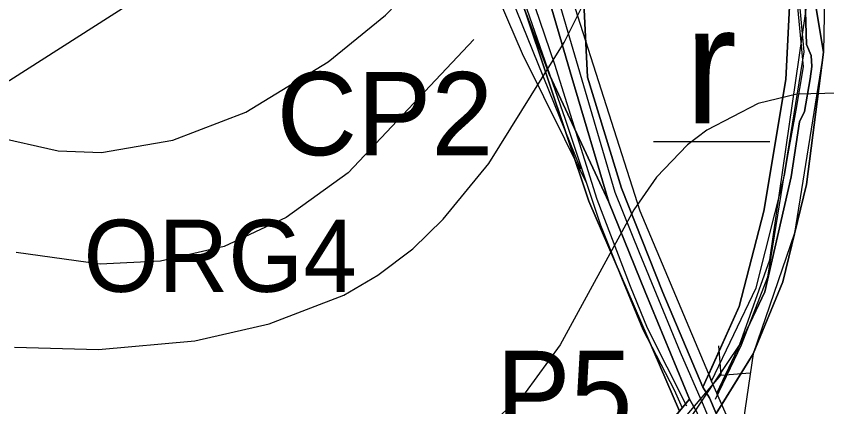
# Model space of a CAD drawing. Extents: x -1900516 to -575031, y -3809306 to -1157387.
# Drawn here: x -577969.3 to -577823.3, y -1159157.5 to -1159087.1 of the extents above; entities that cross this region are included whole.
import ezdxf

# ---------------------------------------------------------------- set-up
doc = ezdxf.new("R2010")
doc.units = 0
for name, color, linetype in [('01_PARCELY_NÁVRH_PC', 7, 'Continuous'), ('01_PARCELY_NÁVRH_VHO', 7, 'Continuous'), ('01_PARCELY_NÁVRH_ŽP', 7, 'Continuous'), ('01_VRSTEVNICE', 7, 'Continuous'), ('01_ZASTAV_PLOCHY', 7, 'Continuous'), ('02_KULTURY STAV', 7, 'Continuous'), ('03_PC_NÁVRH', 7, 'Continuous'), ('03_PC_OBJEKTY_NÁVRH', 7, 'Continuous'), ('04_ZPF_OP_ORGAN', 7, 'Continuous'), ('05_VHO_V_TOK', 7, 'Continuous'), ('06_ÚSES_IP', 7, 'Continuous')]:
    doc.layers.add(name, color=color, linetype=linetype)

msp = doc.modelspace()

# ---------------------------------------------------------------- linework, layer by layer
at = {"layer": '01_PARCELY_NÁVRH_PC'}
for points in [[(-577879.11, -1159080.65), (-577870.41, -1159105.69), (-577866.62, -1159117.03), (-577864.01, -1159124.83), (-577860.26, -1159134.3), (-577856.41, -1159143.62), (-577850.79, -1159154.5), (-577849.3, -1159157.73)], [(-577801.72, -1159250.71), (-577842.19, -1159157.15), (-577843.01, -1159155.26), (-577843.08, -1159155.1), (-577844.01, -1159152.9), (-577844.54, -1159151.63), (-577856.89, -1159122.27), (-577869.01, -1159084.28)]]:
    msp.add_lwpolyline(points, dxfattribs=at)
at = {"layer": '01_PARCELY_NÁVRH_VHO'}
msp.add_lwpolyline([(-577827.31, -1159080.24), (-577826.94, -1159092.24), (-577826.07, -1159094.2), (-577825.96, -1159096.2), (-577826.23, -1159098.41), (-577827.28, -1159104.32), (-577828.19, -1159106.2), (-577829.69, -1159116.08), (-577834.4, -1159136.82), (-577843.08, -1159155.1), (-577844.01, -1159152.9), (-577836, -1159136.1), (-577830.89, -1159115.88), (-577830.21, -1159111.94), (-577828.76, -1159104.07), (-577827.45, -1159096.26), (-577829.3, -1159076.53)], dxfattribs=at)
at = {"layer": '01_PARCELY_NÁVRH_ŽP'}
msp.add_lwpolyline([(-577932.31, -1159000.87), (-577930.98, -1158997.74), (-577917.36, -1159020.44), (-577905.5, -1159036.56), (-577893.55, -1159052.32), (-577884.04, -1159068.85), (-577879.11, -1159080.65), (-577870.41, -1159105.69), (-577866.62, -1159117.03), (-577878.07, -1159093.94), (-577887.72, -1159071.57), (-577897.03, -1159053.79), (-577922.09, -1159016.57)], close=True, dxfattribs=at)
for points in [[(-577829.69, -1159079.32), (-577830.66, -1159098.54), (-577834.61, -1159122.27), (-577839.06, -1159139.48), (-577844.54, -1159151.63), (-577844.01, -1159152.9), (-577836, -1159136.1), (-577830.89, -1159115.88), (-577830.21, -1159111.94), (-577828.76, -1159104.07), (-577827.45, -1159096.26), (-577829.3, -1159076.53)], [(-577823.53, -1159076.95), (-577823.86, -1159093.64), (-577826.94, -1159117.49), (-577831.21, -1159135.01), (-577836.5, -1159148.02), (-577842.19, -1159157.15), (-577843.08, -1159155.1), (-577834.4, -1159136.82), (-577829.69, -1159116.08), (-577828.19, -1159106.2), (-577827.28, -1159104.32), (-577826.23, -1159098.41), (-577825.96, -1159096.2), (-577826.07, -1159094.2), (-577826.94, -1159092.24), (-577827.31, -1159080.24)]]:
    msp.add_lwpolyline(points, dxfattribs=at)
at = {"layer": '01_VRSTEVNICE'}
for points in [[(-578068.7, -1158982.3), (-578057.68, -1158989.5), (-578049.15, -1158997.05), (-578038.8, -1159009.07), (-578032.65, -1159019.42), (-578027.47, -1159032.01), (-578022.16, -1159052.98), (-578018.11, -1159065.56), (-578014.61, -1159073.95), (-578009.58, -1159082.34), (-578003.15, -1159090.45), (-577999.09, -1159094.23), (-577985.25, -1159104.01), (-577973.5, -1159108.77), (-577961.76, -1159111.42), (-577953.93, -1159111.7), (-577941.07, -1159109.47), (-577927.92, -1159104.43), (-577913.1, -1159095.34), (-577902.75, -1159086.95), (-577892.27, -1159076.05)], [(-577969.59, -1159146.8), (-577954.49, -1159147.22), (-577937.15, -1159145.68), (-577923.73, -1159142.6), (-577910.31, -1159137.43), (-577904.15, -1159133.79), (-577897.86, -1159129.04), (-577892.41, -1159123.73), (-577884.16, -1159113.66), (-577870.59, -1159091.85), (-577866.68, -1159084.02), (-577861.51, -1159076.19), (-577854.66, -1159068.36), (-577849.48, -1159063.74), (-577842.63, -1159059.13), (-577836.76, -1159056.61), (-577829.21, -1159054.79), (-577819.14, -1159053.4), (-577800.69, -1159053.82), (-577775.52, -1159058.15), (-577762.09, -1159058.85), (-577746.99, -1159057.03), (-577723.92, -1159050.46)], [(-577886.84, -1159091.34), (-577909.47, -1159115.34), (-577920.65, -1159123.45), (-577931.84, -1159128.62), (-577943.3, -1159131.28), (-577954.21, -1159131.84), (-577969.31, -1159129.74)], [(-577734.13, -1159099.68), (-577756.5, -1159105.97), (-577771.6, -1159108.07), (-577779.99, -1159108.07), (-577795.09, -1159105.97), (-577810.19, -1159102.19), (-577818.58, -1159100.94), (-577828.65, -1159101.22), (-577835.64, -1159102.89), (-577844.87, -1159107.65)], [(-577844.87, -1159107.65), (-577848.36, -1159110.3), (-577853.96, -1159116.18), (-577858.01, -1159122.05), (-577871.3, -1159146.38), (-577877.59, -1159155.05), (-577885.14, -1159161.9), (-577888.77, -1159164.28), (-577895.48, -1159167.35), (-577906.67, -1159170.99), (-577915.62, -1159172.66), (-577926.8, -1159173.78), (-577941.62, -1159173.64), (-577967.63, -1159171.82), (-577997.83, -1159170.85)]]:
    msp.add_lwpolyline(points, dxfattribs=at)
at = {"layer": '01_ZASTAV_PLOCHY'}
msp.add_lwpolyline([(-577900.27, -1159053.87), (-577970.44, -1159098.7), (-578044.57, -1159139.39), (-578076.91, -1159064.93), (-578140.07, -1159108.28), (-578162.92, -1159078.84), (-578172.04, -1159053.77), (-578131.05, -1159028.81), (-578099.98, -1159000.37), (-578085.99, -1159068.04), (-577947.77, -1158984), (-577941.01, -1158994.65), (-577934.61, -1158994.15), (-577921.6, -1159017.6)], close=True, dxfattribs=at)
at = {"layer": '02_KULTURY STAV'}
for points in [[(-577758.96, -1159353.13), (-577779.5, -1159306), (-577804.17, -1159248.7), (-577829.79, -1159191.6), (-577839.47, -1159167.79), (-577843.17, -1159158.72), (-577836.5, -1159148.02), (-577831.21, -1159135.01), (-577826.94, -1159117.49), (-577823.86, -1159093.64), (-577827.04, -1159074.49), (-577828.22, -1159063.62), (-577828.93, -1159050.02), (-577844.85, -1159004.25), (-577848.37, -1158991.08), (-577851.93, -1158977.73), (-577854.57, -1158965.52)], [(-577974.22, -1158998.63), (-577958.28, -1158992.23), (-577941.56, -1158984.96), (-577940.17, -1158988.78), (-577938.98, -1158992.05), (-577933.85, -1158990.91), (-577931, -1158997.18), (-577919.28, -1159016.74), (-577904.08, -1159039.93), (-577901.76, -1159043.18), (-577892.84, -1159056.59), (-577881.84, -1159075.11), (-577873.2, -1159097.68), (-577862.54, -1159120.67), (-577856, -1159136.79), (-577847.98, -1159156.16), (-577860, -1159170.5), (-577866.77, -1159178.55), (-577883.68, -1159198.67), (-577913.2, -1159230.14), (-577932.33, -1159248.38), (-577951.83, -1159268.88), (-577969.57, -1159286.63)], [(-577827.04, -1159074.49), (-577823.86, -1159093.64), (-577826.94, -1159117.49), (-577831.21, -1159135.01), (-577836.5, -1159148.02), (-577843.17, -1159158.72), (-577844.37, -1159155.94), (-577845.62, -1159154.03), (-577839.06, -1159139.48), (-577834.61, -1159122.27), (-577830.66, -1159098.54), (-577829.69, -1159079.32)], [(-577846.76, -1159158.4), (-577847.98, -1159156.16), (-577856, -1159136.79), (-577862.54, -1159120.67), (-577869.19, -1159098.2), (-577873.24, -1159084.45)], [(-577867.12, -1159083.46), (-577866.38, -1159098.11), (-577860.25, -1159118.16), (-577852.83, -1159136.93), (-577845.62, -1159154.03), (-577844.37, -1159155.94), (-577843.17, -1159158.72)], [(-577854.5, -1159109.72), (-577833.5, -1159109.72)]]:
    msp.add_lwpolyline(points, dxfattribs=at)
for points in [[(-577933.85, -1158990.91), (-577920.92, -1159007.59), (-577912.66, -1159018.62), (-577895.94, -1159040.84), (-577888.07, -1159051.95), (-577877.46, -1159071.29), (-577873.24, -1159084.45), (-577869.19, -1159098.2), (-577862.54, -1159120.67), (-577873.2, -1159097.68), (-577881.84, -1159075.11), (-577892.84, -1159056.59), (-577901.76, -1159043.18), (-577904.08, -1159039.93), (-577919.28, -1159016.74), (-577931, -1158997.18)], [(-577933.85, -1158990.91), (-577920.92, -1159007.59), (-577912.66, -1159018.62), (-577895.94, -1159040.84), (-577888.07, -1159051.95), (-577877.46, -1159071.29), (-577873.24, -1159084.45), (-577869.19, -1159098.2), (-577862.54, -1159120.67), (-577873.2, -1159097.68), (-577881.84, -1159075.11), (-577892.84, -1159056.59), (-577901.76, -1159043.18), (-577904.08, -1159039.93), (-577919.28, -1159016.74), (-577931, -1158997.18)], [(-577867.12, -1159083.46), (-577833.47, -1159064.05), (-577832.65, -1159055.55), (-577829.69, -1159079.32), (-577830.66, -1159098.54), (-577834.61, -1159122.27), (-577839.06, -1159139.48), (-577845.62, -1159154.03), (-577852.83, -1159136.93), (-577860.25, -1159118.16), (-577866.38, -1159098.11)], [(-578007.08, -1159333.52), (-577986.84, -1159306.46), (-577969.57, -1159286.63), (-577951.83, -1159268.88), (-577932.33, -1159248.38), (-577913.2, -1159230.14), (-577883.68, -1159198.67), (-577866.77, -1159178.55), (-577860, -1159170.5), (-577847.98, -1159156.16), (-577846.76, -1159158.4), (-577845.76, -1159160.94), (-577860.09, -1159177.9), (-577879.28, -1159200.38), (-577905.69, -1159229.83), (-577929.55, -1159253.23), (-577941.63, -1159265.54), (-577964.41, -1159289.31), (-577983.02, -1159310.9), (-578004.06, -1159336.6)]]:
    msp.add_lwpolyline(points, close=True, dxfattribs=at)
at = {"layer": '03_PC_NÁVRH'}
msp.add_lwpolyline([(-577928.98, -1158993.53), (-577924.18, -1159000.69), (-577917.97, -1159008.87), (-577906.23, -1159023.3), (-577898.05, -1159034.84), (-577890.98, -1159044.78), (-577886.08, -1159051.48), (-577881.03, -1159060.86), (-577875.97, -1159070.24), (-577871.52, -1159084.5), (-577866.48, -1159101.67), (-577861.43, -1159118.84), (-577857.08, -1159129.74), (-577849.7, -1159147.71), (-577845.56, -1159157.17), (-577838.38, -1159174.49), (-577831.19, -1159191.81), (-577822, -1159212.73), (-577810.98, -1159237.28), (-577799.95, -1159261.83), (-577793.6, -1159276.9), (-577787.26, -1159291.98), (-577773.69, -1159323.07), (-577760.12, -1159354.16)], dxfattribs=at)
at = {"layer": '03_PC_OBJEKTY_NÁVRH'}
for points in [[(-577932.9, -1158991.06), (-577930.05, -1158996.73), (-577924.65, -1159005.86), (-577919.92, -1159012.1), (-577915.33, -1159018.95), (-577891.19, -1159051.88), (-577884.61, -1159063.23), (-577880.27, -1159072.45), (-577872.31, -1159095.81), (-577864.68, -1159120.13), (-577858.71, -1159135.82), (-577855.6, -1159143.28), (-577848.57, -1159157.35)], [(-577842.77, -1159146.57), (-577842.36, -1159151.86), (-577837.07, -1159151.44)], [(-577850.47, -1159161.37), (-577842.36, -1159151.86)]]:
    msp.add_lwpolyline(points, dxfattribs=at)
at = {"layer": '04_ZPF_OP_ORGAN'}
for points in [[(-577854.57, -1158965.52), (-577850.96, -1158979.48), (-577848.06, -1158987.7), (-577845.72, -1158992.07), (-577838.92, -1159002.52), (-577836.56, -1159014.23), (-577834.44, -1159029.27), (-577831.01, -1159040.22), (-577827.58, -1159051.16), (-577823.53, -1159076.95), (-577823.86, -1159093.64), (-577829.08, -1159126.25), (-577836.5, -1159148.02), (-577839.19, -1159165.95), (-577812.08, -1159228.47), (-577784.96, -1159291), (-577757.85, -1159353.11)], [(-577854.57, -1158965.52), (-577850.96, -1158979.48), (-577848.06, -1158987.7), (-577845.72, -1158992.07), (-577838.92, -1159002.52), (-577836.56, -1159014.23), (-577834.44, -1159029.27), (-577831.01, -1159040.22), (-577827.58, -1159051.16), (-577823.53, -1159076.95), (-577823.86, -1159093.64), (-577829.08, -1159126.25), (-577836.5, -1159148.02), (-577839.19, -1159165.95), (-577812.08, -1159228.47), (-577784.96, -1159291), (-577757.85, -1159353.11)], [(-577995.92, -1159064.13), (-577935.38, -1159028.44), (-577926.12, -1159023.96), (-577916.8, -1159020.65), (-577891.15, -1159057.33), (-577881.84, -1159075.11), (-577877.52, -1159086.4), (-577866.12, -1159120.5), (-577849.79, -1159158.32), (-577875.23, -1159188.61), (-577904.6, -1159220.3), (-577932.33, -1159248.38), (-577941.68, -1159253.33), (-577953.25, -1159256.11), (-577988.64, -1159195.19)], [(-577988.64, -1159195.19), (-577953.25, -1159256.11), (-577941.68, -1159253.33), (-577932.33, -1159248.38), (-577904.6, -1159220.3), (-577875.23, -1159188.61), (-577849.79, -1159158.32), (-577866.12, -1159120.5), (-577877.52, -1159086.4), (-577881.84, -1159075.11), (-577891.15, -1159057.33), (-577916.8, -1159020.65), (-577926.12, -1159023.96), (-577935.38, -1159028.44), (-577995.92, -1159064.13)]]:
    msp.add_lwpolyline(points, dxfattribs=at)
at = {"layer": '05_VHO_V_TOK'}
for p, q in [((-577830.85, -1159055.43), (-577827.42, -1159093.53)), ((-577827.42, -1159093.53), (-577833.96, -1159134.19)), ((-577833.96, -1159134.19), (-577838.68, -1159146.43)), ((-577838.68, -1159146.43), (-577843.39, -1159156.25))]:
    msp.add_line(p, q, dxfattribs=at)
at = {"layer": '06_ÚSES_IP'}
for points in [[(-577932.03, -1159251.82), (-577889.35, -1159206.35), (-577848.1, -1159159.99), (-577838.99, -1159146.45), (-577833.5, -1159131.04), (-577826.53, -1159082.53), (-577830.28, -1159053.85), (-577846.35, -1158998.36), (-577859.08, -1158969.82), (-577864.84, -1158928.81), (-577870.46, -1158865.96), (-577870.46, -1158839.56), (-577856.93, -1158803.77), (-577813.54, -1158754.32), (-577800.55, -1158720.82), (-577806.18, -1158689.73), (-577786.66, -1158633.2)], [(-577932.31, -1159000.87), (-577888.8, -1159062.4), (-577867.66, -1159114.64)]]:
    msp.add_lwpolyline(points, dxfattribs=at)

# ---------------------------------------------------------------- texts
at = {"layer": '02_KULTURY STAV'}
msp.add_text('r', height=21, dxfattribs=at).set_placement((-577848.82, -1159106.43))
msp.add_text('r', height=21, dxfattribs=at).set_placement((-577848.82, -1159106.43))
at = {"layer": '03_PC_OBJEKTY_NÁVRH'}
for s, p in [('CP2', (-577922.38, -1159112.2)), ('P5', (-577882.82, -1159162.45))]:
    msp.add_text(s, height=15, dxfattribs=at).set_placement(p)
at = {"layer": '04_ZPF_OP_ORGAN'}
msp.add_text('ORG4', height=13, dxfattribs=at).set_placement((-577957.18, -1159136.82))

doc.saveas('drawing.dxf')
